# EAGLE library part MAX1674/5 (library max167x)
Step-Up DC-DC Converter
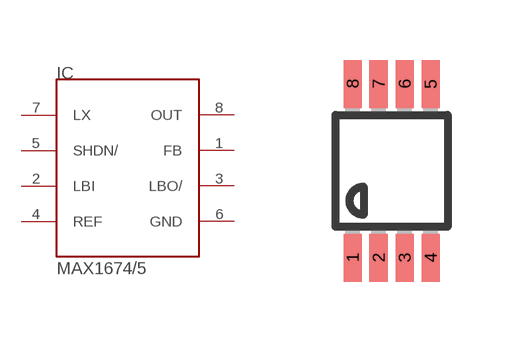
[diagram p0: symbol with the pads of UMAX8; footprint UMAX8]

Designator prefix IC

## MAX1674/5  [UMAX8]
1  FB  in
2  LBI  in
3  LBO/  oc
4  REF  in
5  SHDN/  in
6  GND  pwr
7  LX  in
8  OUT  pas

## Footprint UMAX8 (pad centres in mm)
micro MAX Package
smd 0.45 x 1.2: 1 -0.975,-2.175; 2 -0.325,-2.175; 3 0.325,-2.175; 4 0.975,-2.175; 5 0.975,2.175; 6 0.325,2.175; 7 -0.325,2.175; 8 -0.975,2.175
